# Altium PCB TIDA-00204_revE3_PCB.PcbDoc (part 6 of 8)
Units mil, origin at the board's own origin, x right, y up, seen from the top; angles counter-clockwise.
Board outline 4600 x 3740 mil, 8 copper layers (TopLayer - S1 (.GTL), MidLayer1 - S2 (.G1), MidLayer2 - S3 (.G2), MidLayer3 - S4 (.G3), MidLayer4 - S5 (.G4), MidLayer5 - S6 (.G5), MidLayer6 - S7 (.G6), BottomLayer - S8 (.GBL)), stack 58.938 mil thick; 536 components, 354 nets, 2015 pads, 1067 vias.
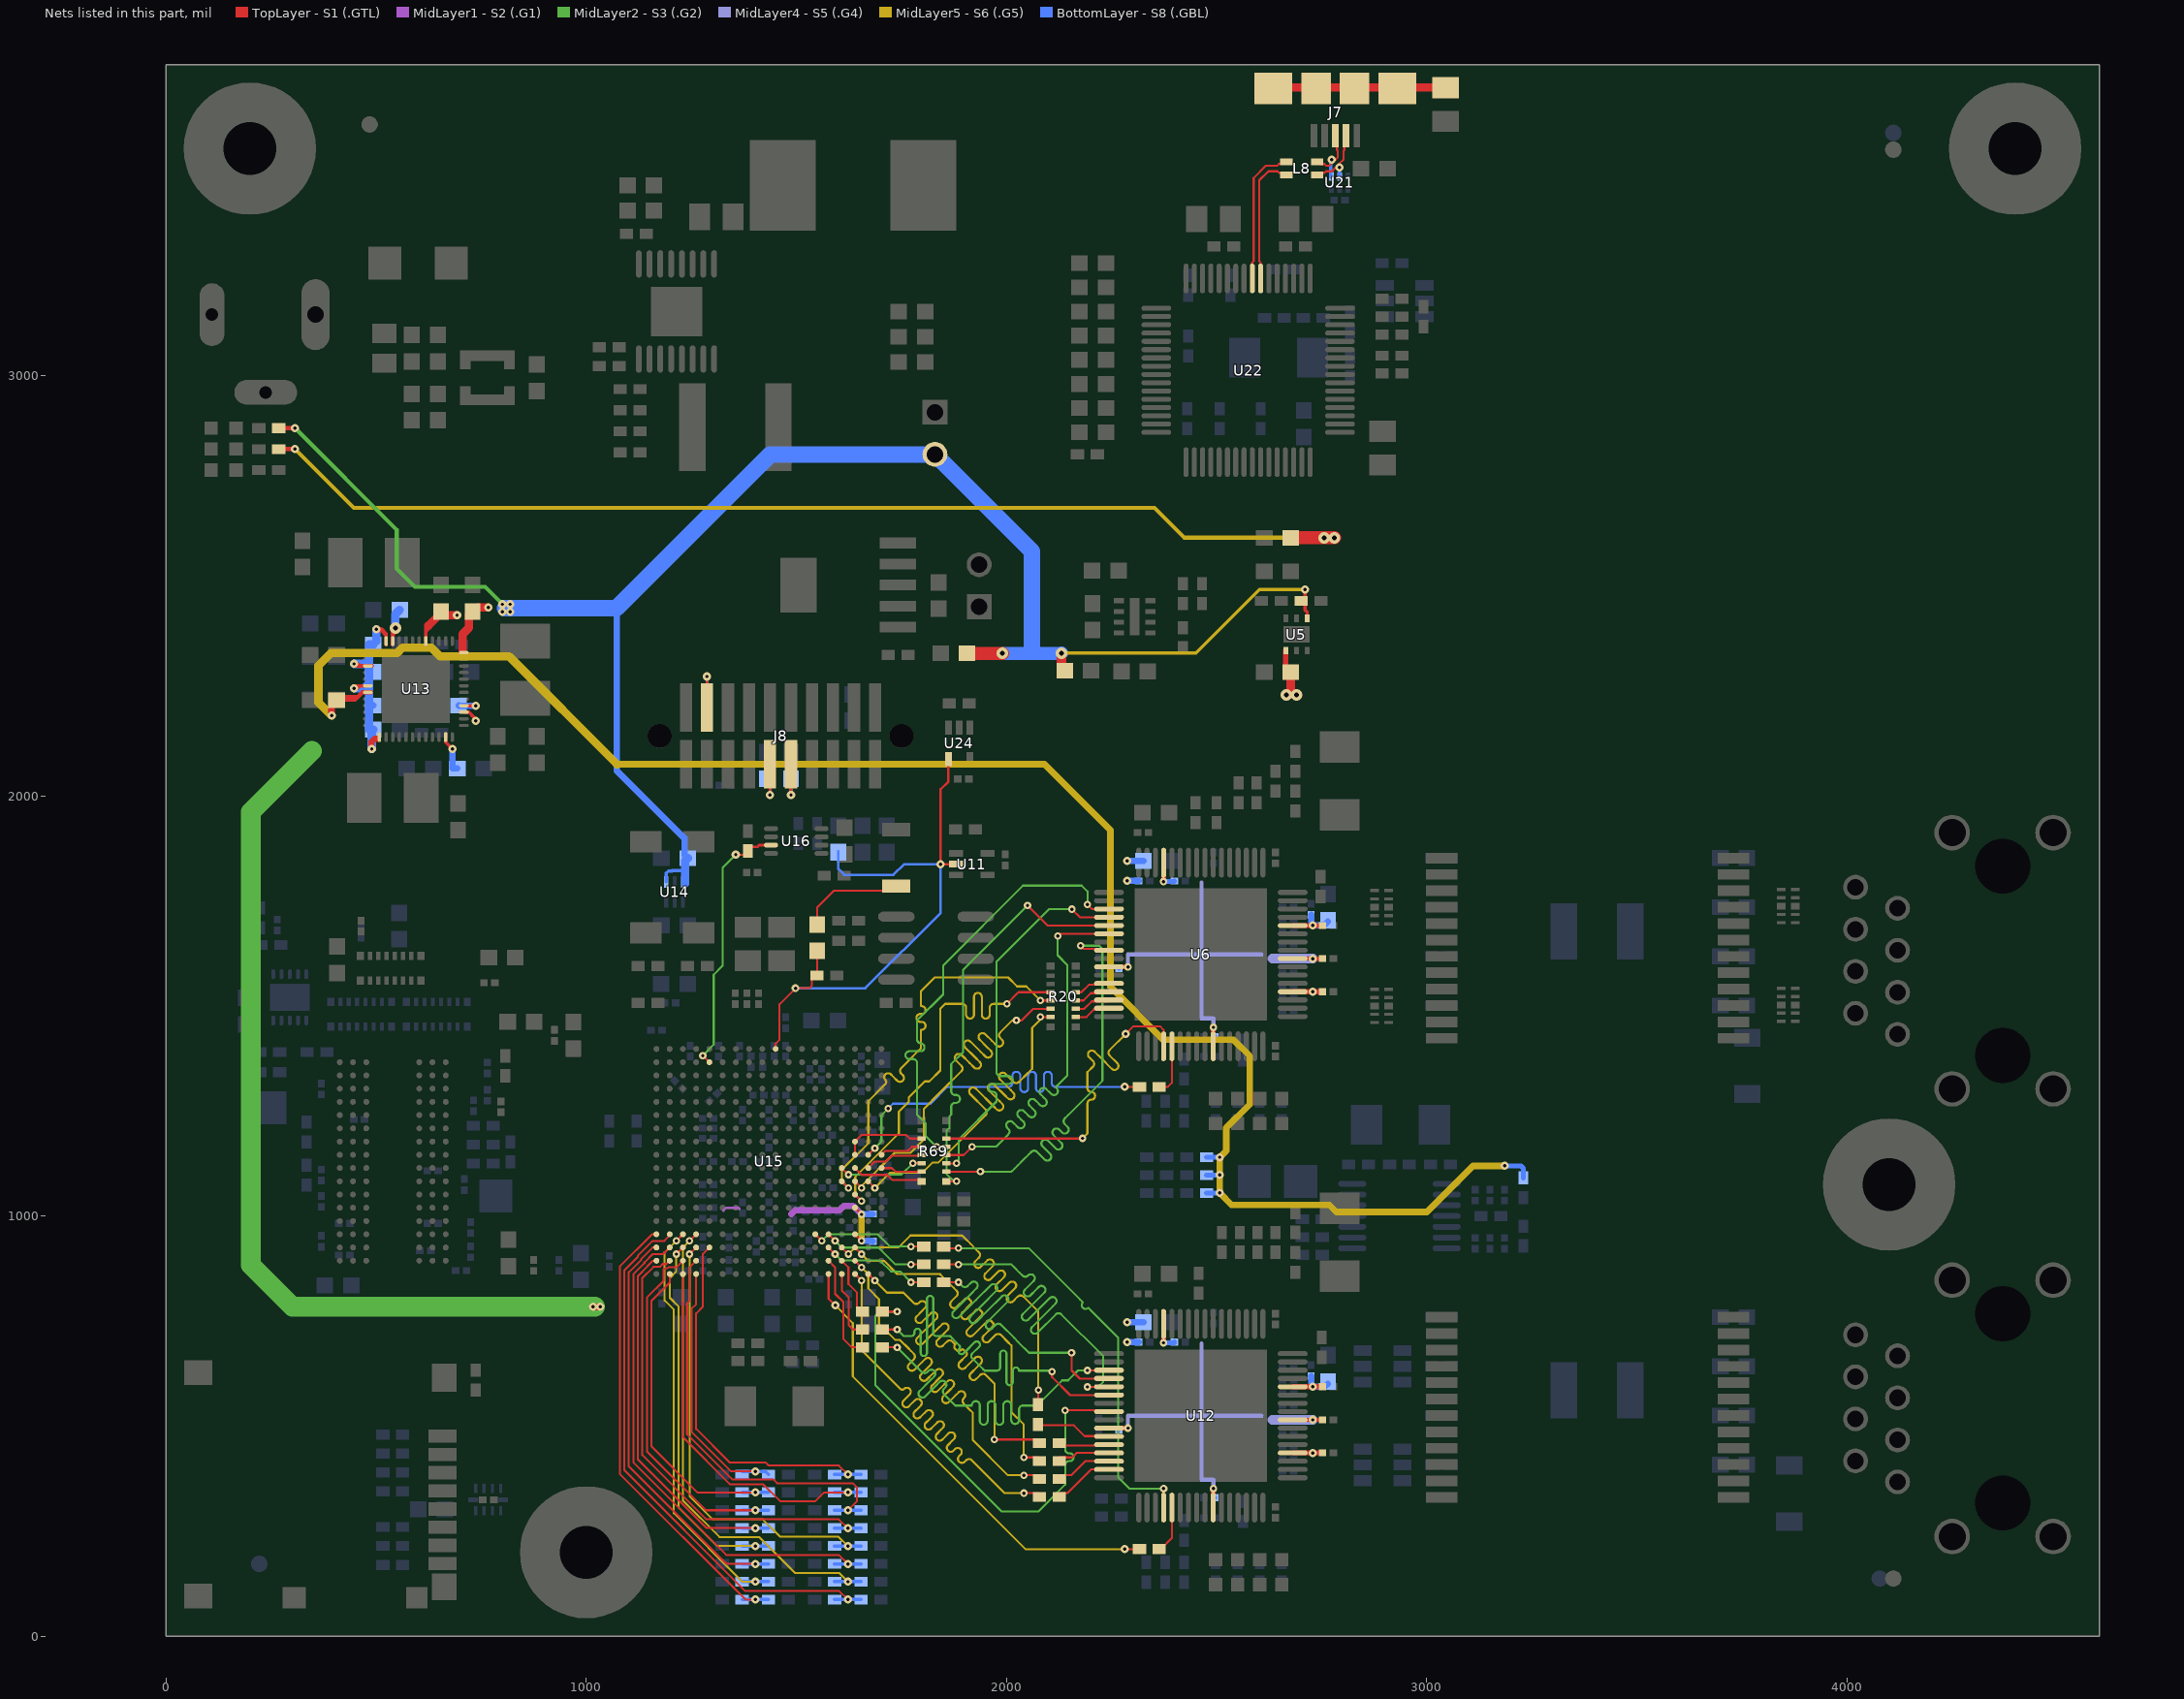
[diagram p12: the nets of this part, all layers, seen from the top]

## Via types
v1: diameter 19.68, hole 7.87, TopLayer - S1 (.GTL) to BottomLayer - S8 (.GBL), 600 vias
v2: diameter 17.72, hole 7.87, TopLayer - S1 (.GTL) to BottomLayer - S8 (.GBL), 408 vias
v3: diameter 27.56, hole 11.81, TopLayer - S1 (.GTL) to BottomLayer - S8 (.GBL), 31 vias
v4: diameter 20, hole 7.87, TopLayer - S1 (.GTL) to BottomLayer - S8 (.GBL), tented both sides, 11 vias
v5: diameter 15.75, hole 7.87, TopLayer - S1 (.GTL) to BottomLayer - S8 (.GBL), 9 vias
v6: diameter 20, hole 7.87, TopLayer - S1 (.GTL) to BottomLayer - S8 (.GBL), 5 vias
v7: diameter 15, hole 7.87, TopLayer - S1 (.GTL) to BottomLayer - S8 (.GBL), 2 vias
v8: diameter 18, hole 7.87, TopLayer - S1 (.GTL) to BottomLayer - S8 (.GBL), 1 vias

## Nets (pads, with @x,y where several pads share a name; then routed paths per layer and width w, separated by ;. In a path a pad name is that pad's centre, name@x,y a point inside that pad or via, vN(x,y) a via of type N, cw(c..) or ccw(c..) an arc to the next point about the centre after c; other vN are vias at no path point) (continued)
RGMII1_RXCTRL: R19.1 U15.J17 | length 965.7
  TopLayer - S1 (.GTL) w4.92: U15.J17@1671.27,1145.75 1674.87,1149.34 v2(1686.99,1161.5) ; v1(2281.32,1307.5) R19.1@2316.38,1307.5
  MidLayer2 - S3 (.G2) w4.68: v2(1686.99,1161.5) 1702.5,1177 1702.5,1239.9 v2(1718.5,1255.91)
  BottomLayer - S8 (.GBL) w4.92: v2(1718.5,1255.91) 1730.1,1267.5 1819.5,1267.5 1859.5,1307.5 2004.92,1307.5 ccw(c2004.92,1316.85) 2014.27,1316.85 2014.27,1334.04 cw(c2023.62,1334.04) 2023.62,1343.39 cw(c2023.62,1334.04) 2032.97,1334.04 2032.97,1307.5 2032.97,1304.46 ccw(c2042.32,1304.46) 2042.32,1295.11 ccw(c2042.32,1304.46) 2051.67,1304.46 2051.67,1307.5 2051.67,1334.04 cw(c2061.02,1334.04) 2061.02,1343.39 cw(c2061.02,1334.04) 2070.37,1334.04 2070.37,1307.5 2070.37,1304.46 ccw(c2079.72,1304.46) 2079.72,1295.11 ccw(c2079.72,1304.46) 2089.07,1304.46 2089.07,1307.5 2089.07,1334.04 cw(c2098.43,1334.04) 2098.43,1343.39 cw(c2098.43,1334.04) 2107.78,1334.04 2107.78,1316.85 ccw(c2117.13,1316.85) 2117.13,1307.5 2166.34,1307.5 v1(2281.32,1307.5)
RGMII1_RXCTRL_R: R19.2 U6.53 | length 121
  TopLayer - S1 (.GTL) w4.92: R19.2@2363.62,1307.5 2384.27,1307.5 2393.6,1316.83 U6.53@2393.6,1404
RGMII1_RXD0: R20.4 U15.M16 | length 1016.2
  TopLayer - S1 (.GTL) w4.92: U15.M16@1639.72,1051.26 v2(1655.47,1035.51) ; v2(2000.98,1504.92) 2026.08,1530.02 2028.72,1532.66 R20.4@2105.47,1532.66
  MidLayer5 - S6 (.G5) w4.92: v2(1655.47,1035.51) 1640.22,1050.77 1640.22,1093.14 1744.09,1197.02 1744.09,1248.58 1767.76,1272.24 1767.76,1282.52 1805.61,1320.37 1816.44,1320.37 1842.52,1346.46 1842.52,1493.11 1854.33,1504.92 1864.17,1504.92 1894.68,1504.92 cw(c1894.68,1495.57) 1904.04,1495.57 1904.04,1479.22 ccw(c1913.39,1479.22) 1913.39,1469.87 ccw(c1913.39,1479.22) 1922.74,1479.22 1922.74,1504.92 1922.74,1521.79 cw(c1932.09,1521.79) 1932.09,1531.14 cw(c1932.09,1521.79) 1941.44,1521.79 1941.44,1504.92 1941.44,1479.22 ccw(c1950.79,1479.22) 1950.79,1469.87 ccw(c1950.79,1479.22) 1960.14,1479.22 1960.14,1495.57 cw(c1969.49,1495.57) 1969.49,1504.92 v2(2000.98,1504.92)
RGMII1_RXD0_R: R20.13 U6.44 | length 88.1
  TopLayer - S1 (.GTL) w4.92: R20.13@2164.53,1532.66 2178.33,1532.66 2195.87,1550.2 2240.59,1550.2 U6.44@2244,1553.6
RGMII1_RXD1: R20.5 U15.L15 | length 1016.9
  TopLayer - S1 (.GTL) w4.92: U15.L15@1608.23,1082.76 v2(1623.98,1067.01) ; v2(2080.89,1512.97) R20.5@2105.47,1512.97
  MidLayer5 - S6 (.G5) w4.92: v2(1623.98,1067.01) 1608.72,1082.26 1608.72,1110.69 1671.26,1173.23 1671.26,1273.62 1710.14,1312.5 1711.93,1314.29 ccw(c1707.11,1319.11) 1711.93,1323.93 cw(c1718.54,1330.54) 1711.93,1337.16 cw(c1718.54,1330.54) 1725.15,1337.16 1729.97,1332.34 1740.12,1322.19 ccw(c1746.73,1328.8) 1753.34,1322.19 ccw(c1746.73,1328.8) 1753.34,1335.41 1749.81,1338.95 cw(c1756.42,1345.56) 1749.81,1352.17 1760.33,1362.7 1796.26,1398.62 1796.26,1415.35 1796.26,1424.7 1796.26,1441.42 cw(c1798.25,1441.42) 1798.25,1443.41 ccw(c1798.25,1452.76) 1807.6,1452.76 ccw(c1798.25,1452.76) 1798.25,1462.11 1796.26,1462.11 1795.12,1462.11 cw(c1795.12,1471.46) 1785.77,1471.46 cw(c1795.12,1471.46) 1795.12,1480.81 1796.26,1480.81 1798.25,1480.81 ccw(c1798.25,1490.16) 1807.6,1490.16 ccw(c1798.25,1490.16) 1798.25,1499.51 cw(c1798.25,1501.5) 1796.26,1501.5 1796.26,1518.21 1796.26,1534.45 1829.72,1567.91 1882.87,1567.91 1970.47,1567.91 2004.02,1567.91 2025.48,1546.46 2047.4,1546.46 v2(2080.89,1512.97)
RGMII1_RXD1_R: R20.12 U6.45 | length 88.1
  TopLayer - S1 (.GTL) w4.92: R20.12@2164.53,1512.97 2183.25,1512.97 2200.79,1530.51 2240.59,1530.51 U6.45@2244,1533.92
RGMII1_RXD2: R20.6 U15.L16 | length 1009.7
  TopLayer - S1 (.GTL) w4.92: U15.L16@1639.72,1082.76 v2(1655.47,1067.01) ; v2(2023.62,1465.55) 2036.42,1465.55 2064.15,1493.29 R20.6@2105.47,1493.29
  MidLayer5 - S6 (.G5) w4.92: v2(1655.47,1067.01) 1655.47,1071.81 1734.25,1150.59 1771.65,1150.59 1803.35,1182.28 1803.35,1255.03 1841.58,1293.26 1892.67,1344.36 ccw(c1886.06,1350.97) 1892.67,1357.58 1880.18,1370.08 cw(c1886.79,1376.69) 1880.18,1383.3 cw(c1886.79,1376.69) 1893.4,1383.3 1912.51,1364.19 1923.31,1353.39 ccw(c1929.92,1360.01) 1936.53,1353.39 ccw(c1929.92,1360.01) 1936.53,1366.62 1925.73,1377.42 1901.21,1401.94 cw(c1907.82,1408.55) 1901.21,1415.16 cw(c1907.82,1408.55) 1914.43,1415.16 1938.95,1390.64 1949.75,1379.84 ccw(c1956.36,1386.45) 1962.98,1379.84 ccw(c1956.36,1386.45) 1962.98,1393.07 1952.18,1403.86 1936.51,1419.54 cw(c1943.12,1426.15) 1936.51,1432.76 cw(c1943.12,1426.15) 1949.73,1432.76 1965.4,1417.09 1976.2,1406.29 ccw(c1982.81,1412.9) 1989.42,1406.29 ccw(c1982.81,1412.9) 1989.42,1419.51 1985.24,1423.7 cw(c1991.85,1430.31) 1985.24,1436.92 2013.87,1465.55 v2(2023.62,1465.55)
RGMII1_RXD2_R: R20.11 U6.46 | length 88.1
  TopLayer - S1 (.GTL) w4.92: R20.11@2164.53,1493.29 2185.22,1493.29 2202.76,1510.83 2240.59,1510.83 U6.46@2244,1514.23
RGMII1_RXD3: R20.7 U15.L17 | length 1016.2
  TopLayer - S1 (.GTL) w4.92: U15.L17@1671.22,1082.76 v2(1686.97,1067.01) ; v2(2080.89,1473.6) R20.7@2105.47,1473.6
  MidLayer5 - S6 (.G5) w4.92: v2(1686.97,1067.01) 1723.31,1103.35 1800.2,1103.35 1823.82,1126.97 1837.6,1126.97 1917.82,1207.18 1950.74,1240.11 ccw(c1944.13,1246.72) 1950.74,1253.34 1914.12,1289.96 cw(c1920.73,1296.57) 1914.12,1303.19 cw(c1920.73,1296.57) 1927.34,1303.19 1970.58,1259.95 1976.65,1253.87 ccw(c1983.26,1260.48) 1989.88,1253.87 ccw(c1983.26,1260.48) 1989.88,1267.1 1983.8,1273.17 1958.26,1298.71 cw(c1964.87,1305.32) 1958.26,1311.93 cw(c1964.87,1305.32) 1971.49,1311.93 1997.02,1286.39 2003.1,1280.32 ccw(c2009.71,1286.93) 2016.32,1280.32 ccw(c2009.71,1286.93) 2016.32,1293.54 2010.25,1299.62 1984.71,1325.16 cw(c1991.32,1331.77) 1984.71,1338.38 cw(c1991.32,1331.77) 1997.93,1338.38 2016.86,1319.45 ccw(c2023.47,1326.07) 2030.08,1319.45 2036.7,1326.07 2043.31,1332.68 2061.02,1350.39 2061.02,1447.83 2080.89,1467.7 v2(2080.89,1473.6)
RGMII1_RXD3_R: R20.10 U6.47 | length 88.1
  TopLayer - S1 (.GTL) w4.92: R20.10@2164.53,1473.6 2190.14,1473.6 2207.68,1491.14 2240.59,1491.14 U6.47@2244,1494.55
RGMII1_TXCLK: R69.10 U6.40 | length 1066
  TopLayer - S1 (.GTL) w4.92: R69.10@1857.03,1105.79 v2(1938.21,1105.79) ; v2(2176.5,1643.5) 2184.11,1635.89 U6.40@2224.34,1635.89
  MidLayer2 - S3 (.G2) w4.92: v2(1938.21,1105.79) 2012.28,1105.79 2019.68,1113.19 2026.3,1119.8 2039.52,1133.02 2052.74,1146.25 2059.36,1152.86 cw(c2065.97,1146.25) 2072.58,1152.86 2090.71,1134.73 ccw(c2097.32,1141.34) 2103.94,1134.73 ccw(c2097.32,1141.34) 2103.94,1147.95 2085.8,1166.08 cw(c2092.41,1172.69) 2085.8,1179.31 cw(c2092.41,1172.69) 2099.03,1179.31 2117.16,1161.17 ccw(c2123.77,1167.78) 2130.38,1161.17 ccw(c2123.77,1167.78) 2130.38,1174.4 2112.25,1192.53 cw(c2118.86,1199.14) 2112.25,1205.75 cw(c2118.86,1199.14) 2125.47,1205.75 2132.05,1199.18 ccw(c2138.66,1205.79) 2145.27,1199.18 ccw(c2138.66,1205.79) 2145.27,1212.4 2138.7,1218.98 cw(c2145.31,1225.59) 2138.7,1232.2 2146.16,1239.67 2228.35,1321.85 2228.35,1635.83 2220.67,1643.5 v2(2176.5,1643.5)
RGMII1_TXCLK_R: R69.7 U15.K18 | length 98.8
  TopLayer - S1 (.GTL) w4.92: U15.K18@1702.72,1114.25 1727.28,1114.25 1735.75,1105.79 R69.7@1797.97,1105.79
RGMII1_TXCTRL: R69.14 U6.52 | length 904.4
  TopLayer - S1 (.GTL) w4.92: R69.14@1857.03,1184.53 2180.59,1184.53 v2(2181.1,1185.04) ; v1(2283.46,1433.07) 2302.17,1451.77 2365.16,1451.77 2373.92,1443.01 U6.52@2373.92,1404
  MidLayer5 - S6 (.G5) w4.92: v2(2181.1,1185.04) 2192.72,1196.65 2192.72,1253.94 2192.72,1267.97 cw(c2201.62,1267.97) 2201.62,1276.87 ccw(c2201.62,1286.22) 2210.97,1286.22 ccw(c2201.62,1286.22) 2201.62,1295.57 cw(c2201.62,1304.47) 2192.72,1304.47 2192.72,1314.27 2192.72,1332.97 2192.72,1342.32 2205.9,1355.51 ccw(c2199.29,1362.12) 2205.9,1368.73 2196.69,1377.94 cw(c2203.3,1384.55) 2196.69,1391.16 cw(c2203.3,1384.55) 2209.92,1391.16 2225.74,1375.34 2250.48,1350.6 ccw(c2257.09,1357.21) 2263.7,1350.6 ccw(c2257.09,1357.21) 2263.7,1363.82 2245.57,1381.95 cw(c2252.18,1388.57) 2245.57,1395.18 v1(2283.46,1433.07)
RGMII1_TXCTRL_R: R69.3 U15.H16 U15.J16 | length 199.8
  TopLayer - S1 (.GTL) w4.92: U15.J16@1639.72,1145.75 U15.H16@1639.72,1177.24 1655.48,1193 1761.72,1193 1770.2,1184.53 R69.3@1797.97,1184.53
RGMII1_TXD0: R69.12 U6.38 | length 1050
  TopLayer - S1 (.GTL) w4.68: v2(2122.05,1666.34) 2127.42,1671.71 2209.71,1671.71 U6.38@2216.54,1671.71
  TopLayer - S1 (.GTL) w4.92: R69.12@1857.03,1145.16 1898.35,1145.16 v2(1918.21,1165.02) ; U6.38@2209.71,1671.71 U6.38@2244,1671.71
  MidLayer2 - S3 (.G2) w4.92: v2(1918.21,1165.02) 1975.06,1165.02 2004.43,1194.39 ccw(c1997.82,1201) 2004.43,1207.61 2002.17,1209.87 cw(c2008.78,1216.49) 2002.17,1223.1 cw(c2008.78,1216.49) 2015.39,1223.1 2024.26,1214.22 2027.05,1211.44 ccw(c2033.66,1218.05) 2040.27,1211.44 ccw(c2033.66,1218.05) 2040.27,1224.67 2037.49,1227.45 2028.62,1236.32 cw(c2035.23,1242.93) 2028.62,1249.54 cw(c2035.23,1242.93) 2041.84,1249.54 2050.71,1240.67 2053.49,1237.89 ccw(c2060.11,1244.5) 2066.72,1237.89 ccw(c2060.11,1244.5) 2066.72,1251.11 2063.93,1253.9 2055.06,1262.77 cw(c2061.67,1269.38) 2055.06,1275.99 cw(c2061.67,1269.38) 2068.29,1275.99 2077.16,1267.12 2079.94,1264.34 ccw(c2086.55,1270.95) 2093.16,1264.34 ccw(c2086.55,1270.95) 2093.16,1277.56 2090.38,1280.34 2081.51,1289.21 cw(c2088.12,1295.83) 2081.51,1302.44 cw(c2088.12,1295.83) 2094.73,1302.44 2103.6,1293.57 2106.39,1290.78 ccw(c2113,1297.39) 2119.61,1290.78 ccw(c2113,1297.39) 2119.61,1304.01 cw(c2122.39,1306.79) 2119.61,1309.57 2131.89,1321.85 2144.79,1334.75 2144.79,1597.54 2121.58,1620.75 v2@2121.58,1666.25
RGMII1_TXD0_R: R69.5 U15.K17 | length 137.5
  TopLayer - S1 (.GTL) w4.92: U15.K17@1671.22,1114.25 1686.97,1130 1713.45,1130 1727.15,1143.7 R69.5@1796.52,1143.7
RGMII1_TXD1: R69.9 U6.37 | length 1011.3
  TopLayer - S1 (.GTL) w4.92: R69.9@1857.03,1082.66 v2(1881.61,1082.66) ; v2@2052.17,1737.2 2097.97,1691.4 U6.37@2244,1691.4
  MidLayer2 - S3 (.G2) w4.92: v2(1881.61,1082.66) 1875.04,1082.66 1857.3,1100.41 1857.3,1202.88 1864.78,1210.36 1864.78,1237.63 1868.58,1241.44 1868.58,1250.79 1868.58,1260.14 cw(c1877.93,1260.14) 1877.93,1269.49 1880.05,1269.49 ccw(c1880.05,1278.84) 1889.4,1278.84 ccw(c1880.05,1278.84) 1880.05,1288.19 1877.93,1288.19 cw(c1877.93,1297.54) 1868.58,1297.54 1868.58,1345.47 1868.58,1361.69 1896.65,1389.76 1896.65,1585.63 v2(2050.2,1739.17)
RGMII1_TXD1_R: R69.8 U15.K16 | length 167.2
  TopLayer - S1 (.GTL) w4.92: U15.K16@1639.72,1114.25 1655.98,1098 1716.96,1098 1729.33,1085.63 R69.8@1795,1085.63
RGMII1_TXD2: R69.11 U6.36 | length 959.5
  TopLayer - S1 (.GTL) w4.68: v2(2155.51,1730.32) 2174.74,1711.08
  TopLayer - S1 (.GTL) w4.92: R69.11@1857.03,1125.47 v2(1881.61,1125.47) ; 2174.74,1711.08 U6.36@2244,1711.08
  MidLayer2 - S3 (.G2) w4.92: v2(1881.61,1125.47) 1886.81,1130.67 1886.81,1183.01 1976.38,1272.57 1976.38,1286.42 ccw(c1967.03,1286.42) 1967.03,1295.77 cw(c1967.03,1305.12) 1957.68,1305.12 cw(c1967.03,1305.12) 1967.03,1314.47 1976.38,1314.47 2004.58,1314.47 ccw(c2004.58,1323.82) 2013.93,1323.82 ccw(c2004.58,1323.82) 2004.58,1333.17 1985.73,1333.17 cw(c1985.73,1342.52) 1976.38,1342.52 1976.38,1396.65 1976.38,1605.32 2101.38,1730.32 v2(2155.51,1730.32)
RGMII1_TXD2_R: R69.6 U15.K15 | length 207.2
  TopLayer - S1 (.GTL) w4.92: U15.K15@1608.23,1114.25 v2(1623.98,1098.5) ; v2(1777.56,1125.98) R69.6@1797.46,1125.98
  MidLayer2 - S3 (.G2) w4.68: v2(1623.98,1098.5) 1750.08,1098.5 v2(1777.56,1125.98)
RGMII1_TXD3: R69.13 U6.35 | length 1083.7
  TopLayer - S1 (.GTL) w4.92: v2(1833.66,1164.37) 1834.13,1164.84 R69.13@1857.03,1164.84 ; v2(2192.91,1741.14) 2203.29,1730.77 U6.35@2244,1730.77
  MidLayer2 - S3 (.G2) w4.92: v2(1833.66,1164.37) 1808.27,1189.76 1808.27,1220.47 1787.4,1241.35 1787.4,1364.17 ccw(c1778.05,1364.17) 1778.05,1373.52 1769.16,1373.52 cw(c1769.16,1382.87) 1759.81,1382.87 cw(c1769.16,1382.87) 1769.16,1392.22 1787.4,1392.22 1795.59,1392.22 ccw(c1795.59,1401.57) 1804.94,1401.57 ccw(c1795.59,1401.57) 1795.59,1410.93 1796.74,1410.93 cw(c1796.75,1420.28) 1787.4,1420.28 1787.4,1429.13 1787.4,1465.55 1849.41,1527.56 1849.41,1596.46 2039.37,1786.42 2179.13,1786.42 2192.91,1772.64 v2(2192.91,1741.14)
RGMII1_TXD3_R: R69.4 U15.J18 | length 103.2
  TopLayer - S1 (.GTL) w4.92: U15.J18@1702.72,1145.75 1711.97,1155 1765.24,1155 1775.08,1164.84 R69.4@1797.97,1164.84
RGMII2_RXCLK: R44.1 U15.T15 | length 1047.9
  TopLayer - S1 (.GTL) w4.92: U15.T15@1608.23,925.28 v2@1623.95,909.57 ; v2@2075.79,585.04 2075.79,548.23 R44.1@2076.38,547.64
  MidLayer5 - S6 (.G5) w4.92: v2(1623.97,909.55) 1639.62,925.2 1743.11,925.2 1771.65,953.74 1894.68,953.74 1901.3,947.13 1914.52,933.91 1927.74,920.68 1934.36,914.07 cw(c1927.74,907.46) 1934.36,900.85 1926.03,892.53 ccw(c1932.65,885.91) 1926.03,879.3 ccw(c1932.65,885.91) 1939.26,879.3 1954.19,894.23 cw(c1960.8,887.62) 1967.41,894.23 cw(c1960.8,887.62) 1967.41,881.01 1950.1,863.69 ccw(c1956.71,857.08) 1950.1,850.47 ccw(c1956.71,857.08) 1963.32,850.47 1980.64,867.79 cw(c1987.25,861.18) 1993.86,867.79 cw(c1987.25,861.18) 1993.86,854.56 1976.54,837.25 ccw(c1983.15,830.63) 1976.54,824.02 ccw(c1983.15,830.63) 1989.77,824.02 2007.08,841.34 cw(c2013.7,834.73) 2020.31,841.34 cw(c2013.7,834.73) 2020.31,828.12 2002.99,810.8 ccw(c2009.6,804.19) 2002.99,797.58 ccw(c2009.6,804.19) 2016.21,797.58 2026.92,808.28 cw(c2033.53,801.67) 2040.14,808.28 2072.34,776.08 2075.79,772.64 v2(2075.79,585.63)
RGMII2_RXCLK_R: R44.2 U12.43 | length 155.3
  TopLayer - S1 (.GTL) w4.92: R44.2@2082.61,501.43 2083.14,501.97 2160.43,501.97 2186.02,476.38 2226.25,476.38 U12.43@2226.84,475.79
RGMII2_RXCTRL: R43.1 U15.V14 | length 1119.9
  TopLayer - S1 (.GTL) w4.92: U15.V14@1576.73,862.28 1576.73,803.27 v1(1592.5,787.5) ; v1(2281.32,207.5) R43.1@2316.38,207.5
  MidLayer5 - S6 (.G5) w4.68: v1(1592.5,787.5) 1634.5,745.5 1634.5,618.45 2045.45,207.5 v1(2281.32,207.5)
RGMII2_RXCTRL_R: R43.2 U12.53 | length 113.7
  TopLayer - S1 (.GTL) w4.92: R43.2@2363.62,207.5 2367.5,207.5 2393.6,233.6 U12.53@2393.6,306.5
RGMII2_RXD0: R46.1 U15.V17 | length 1108.8
  TopLayer - S1 (.GTL) w4.92: U15.V17@1671.22,862.28 v2(1686.97,846.56) ; v2(1971.46,468.5) 1971.63,468.33 R46.1@2076.38,468.33
  MidLayer5 - S6 (.G5) w4.92: v2(1686.97,846.56) 1715.61,817.91 1754.92,817.91 1779.04,793.8 ccw(c1785.65,800.41) 1792.26,793.8 1793.4,794.94 cw(c1800.02,788.33) 1806.63,794.94 cw(c1800.02,788.33) 1806.63,781.72 1798.87,773.96 1786.39,761.48 ccw(c1793,754.87) 1786.39,748.26 ccw(c1793,754.87) 1799.61,748.26 1812.09,760.74 1819.85,768.5 cw(c1826.46,761.89) 1833.08,768.5 cw(c1826.46,761.89) 1833.08,755.28 1825.32,747.52 1788.01,710.21 ccw(c1794.62,703.6) 1788.01,696.99 ccw(c1794.62,703.6) 1801.23,696.99 1838.54,734.29 1846.3,742.05 cw(c1852.91,735.44) 1859.52,742.05 cw(c1852.91,735.44) 1859.52,728.83 1851.76,721.07 1835.81,705.11 ccw(c1842.42,698.5) 1835.81,691.89 ccw(c1842.42,698.5) 1849.03,691.89 1858.38,701.24 cw(c1864.99,694.62) 1871.6,701.23 1878.21,694.62 ccw(c1883.68,689.16) 1878.21,683.7 1880.51,681.4 ccw(c1885.97,686.86) 1891.43,681.4 cw(c1895.03,677.8) 1898.63,681.4 1904.66,675.37 cw(c1901.06,671.77) 1904.66,668.18 1888.7,652.22 ccw(c1895.31,645.61) 1888.7,639 ccw(c1895.31,645.61) 1901.92,639 1917.88,654.95 1925.64,662.71 cw(c1932.25,656.1) 1938.86,662.71 cw(c1932.25,656.1) 1938.86,649.49 1931.11,641.73 1915.15,625.77 ccw(c1921.76,619.16) 1915.15,612.55 ccw(c1921.76,619.16) 1928.37,612.55 1937.72,621.89 cw(c1944.33,615.28) 1950.94,621.89 1969,603.84 1971.46,601.38 v2(1971.46,468.5)
RGMII2_RXD0_R: R46.2 U12.44 | length 127.4
  TopLayer - S1 (.GTL) w4.92: R46.2@2123.62,468.33 2138.21,453.74 2241.63,453.74 U12.44@2244,456.1
RGMII2_RXD1: R47.1 U15.T16 | length 1103.2
  TopLayer - S1 (.GTL) w4.92: U15.T16@1639.72,925.28 v2(1655.47,909.53) ; v2(2041.32,425.83) R47.1@2076.38,425.83
  MidLayer5 - S6 (.G5) w4.92: v2(1655.47,909.53) 1671.69,893.31 1709.05,893.31 1740.16,862.2 1841.54,862.2 1848.15,855.59 1861.37,842.37 1874.59,829.15 1881.21,822.53 cw(c1874.59,815.92) 1881.21,809.31 1868.75,796.86 ccw(c1875.37,790.25) 1868.75,783.64 ccw(c1875.37,790.25) 1881.98,783.64 1901.04,802.7 cw(c1906.14,797.6) 1911.24,802.7 1914.26,799.68 cw(c1909.16,794.58) 1914.26,789.48 1895.2,770.41 ccw(c1901.81,763.8) 1895.2,757.19 ccw(c1901.81,763.8) 1908.42,757.19 1927.49,776.25 cw(c1932.59,771.15) 1937.69,776.25 1940.71,773.23 cw(c1935.61,768.13) 1940.71,763.03 1907.58,729.9 ccw(c1914.19,723.29) 1907.58,716.68 ccw(c1914.19,723.29) 1920.81,716.68 1953.93,749.81 cw(c1959.03,744.71) 1964.13,749.81 1967.16,746.78 cw(c1962.06,741.68) 1967.16,736.58 1945.89,715.31 ccw(c1952.5,708.7) 1945.89,702.09 ccw(c1952.5,708.7) 1959.11,702.09 1973.77,716.75 cw(c1980.38,710.13) 1986.99,716.75 2002.95,700.79 2011.81,691.93 2011.81,533.46 2041.32,503.96 v2(2041.32,425.83)
RGMII2_RXD1_R: R47.2 U12.45 | length 124.8
  TopLayer - S1 (.GTL) w4.92: R47.2@2123.62,425.83 2156.14,425.83 2166.73,436.42 U12.45@2244,436.42
RGMII2_RXD2: R50.1 U15.U16 | length 1108.9
  TopLayer - S1 (.GTL) w4.92: U15.U16@1639.72,893.78 v2@1655.45,878.07 ; v2(2041.32,383.33) R50.1@2076.38,383.33
  MidLayer5 - S6 (.G5) w4.92: v2(1655.47,878.05) 1671.26,862.26 1671.26,827.76 1696.85,802.17 1696.85,744.09 1735.99,704.96 1747.04,704.96 1766.35,685.64 ; 1749.02,702.98 1766.35,685.64 ; v2(2041.32,383.33) 2003.48,383.33 1920.28,466.54 1920.28,531.72 1911.53,540.47 1898.59,553.41 cw(c1905.2,560.02) 1898.59,566.63 1899.26,567.3 ccw(c1892.65,573.92) 1899.26,580.53 ccw(c1892.65,573.92) 1886.04,580.53 1878.75,573.24 1862.91,557.41 cw(c1856.3,564.02) 1849.69,557.41 cw(c1856.3,564.02) 1849.69,570.63 1865.53,586.47 1872.81,593.75 ccw(c1866.2,600.36) 1872.81,606.98 ccw(c1866.2,600.36) 1859.59,606.98 1852.3,599.69 1836.47,583.85 cw(c1829.86,590.47) 1823.24,583.85 cw(c1829.86,590.47) 1823.24,597.08 1839.08,612.91 1846.37,620.2 ccw(c1839.75,626.81) 1846.37,633.42 ccw(c1839.75,626.81) 1833.14,633.42 1825.86,626.14 1810.38,610.66 cw(c1803.77,617.28) 1797.16,610.66 cw(c1803.77,617.28) 1797.16,623.89 1812.63,639.36 1819.92,646.65 ccw(c1813.31,653.26) 1819.92,659.87 ccw(c1813.31,653.26) 1806.69,659.87 1799.41,652.58 1781.45,634.62 cw(c1774.84,641.23) 1768.23,634.62 cw(c1774.84,641.23) 1768.23,647.85 1779.57,659.2 ccw(c1772.96,665.81) 1779.57,672.42 1772.96,679.03 1766.35,685.64
RGMII2_RXD2_R: R50.2 U12.46 | length 134.2
  TopLayer - S1 (.GTL) w4.92: R50.2@2123.62,383.33 2154,383.33 2187.4,416.73 U12.46@2244,416.73
RGMII2_RXD3: R51.1 U15.V16 | length 1084.3
  TopLayer - S1 (.GTL) w4.92: U15.V16@1639.76,862.28 v2(1655.46,846.58) ; v2(2041.32,340.83) R51.1@2076.38,340.83
  MidLayer5 - S6 (.G5) w4.92: v2(1655.46,846.58) 1655.46,681.15 1745.57,591.04 1747.78,588.83 ccw(c1752.18,593.24) 1756.58,588.83 cw(c1763.2,582.22) 1769.81,588.83 cw(c1763.2,582.22) 1769.81,575.61 1765.41,571.21 1755.16,560.96 ccw(c1761.77,554.35) 1755.16,547.74 ccw(c1761.77,554.35) 1768.38,547.74 1778.63,557.98 1782.67,562.02 cw(c1789.28,555.41) 1795.89,562.02 cw(c1789.28,555.41) 1795.89,548.8 1791.85,544.76 1781.61,534.51 ccw(c1788.22,527.9) 1781.61,521.29 ccw(c1788.22,527.9) 1794.83,521.29 1805.08,531.54 1809.12,535.58 cw(c1815.73,528.96) 1822.34,535.58 cw(c1815.73,528.96) 1822.34,522.35 1818.3,518.31 1808.05,508.07 ccw(c1814.66,501.46) 1808.05,494.84 ccw(c1814.66,501.46) 1821.28,494.84 1831.52,505.09 1835.56,509.13 cw(c1842.17,502.52) 1848.79,509.13 cw(c1842.17,502.52) 1848.79,495.91 1844.75,491.87 1834.5,481.62 ccw(c1841.11,475.01) 1834.5,468.4 ccw(c1841.11,475.01) 1847.72,468.4 1857.97,478.64 1862.01,482.68 cw(c1868.62,476.07) 1875.23,482.68 cw(c1868.62,476.07) 1875.23,469.46 1871.19,465.42 1860.95,455.17 ccw(c1867.56,448.56) 1860.95,441.95 ccw(c1867.56,448.56) 1874.17,441.95 1877.81,445.59 cw(c1884.42,438.97) 1891.03,445.59 cw(c1884.42,438.97) 1891.03,432.36 1887.39,428.73 ccw(c1894,422.11) 1887.39,415.5 ccw(c1894,422.11) 1900.62,415.5 1904.25,419.14 cw(c1910.86,412.53) 1917.48,419.14 1928.64,407.97 1995.79,340.83 v2(2041.32,340.83)
RGMII2_RXD3_R: R51.2 U12.47 | length 143.7
  TopLayer - S1 (.GTL) w4.92: R51.2@2123.62,340.83 2144.96,340.83 2201.18,397.05 U12.47@2244,397.05
RGMII2_TXCLK: R82.2 U12.40 | length 1145.8
  TopLayer - S1 (.GTL) w4.92: R82.2@1704.84,772.73 v2(1739.9,772.73) ; v2@2137.8,537.4 2138.78,538.39 U12.40@2224.34,538.39
  MidLayer2 - S3 (.G2) w4.92: v2(1739.9,772.73) 1698.91,772.73 1687.99,761.81 1687.99,597.44 1988.19,297.24 2075.79,297.24 2139.76,361.22 2139.76,407.48 cw(c2149.11,407.48) 2149.11,416.83 2150.52,416.83 ccw(c2150.52,426.18) 2159.87,426.18 ccw(c2150.52,426.18) 2150.52,435.53 2149.11,435.53 cw(c2149.11,444.88) 2139.76,444.88 v2(2139.76,537.4)
RGMII2_TXCLK_R: R82.1 U15.U15 | length 146.3
  TopLayer - S1 (.GTL) w4.92: U15.U15@1608.23,893.78 1623.99,878.04 1623.99,838.61 1644.68,817.91 1644.68,777.56 1649.51,772.73 R82.1@1657.6,772.73
RGMII2_TXCTRL: R77.2 U12.52 | length 1009.9
  TopLayer - S1 (.GTL) w4.92: R77.2@1850.78,923.56 v2(1885.84,923.56) ; U12.52@2373.92,306.5 2373.92,350.92 v2@2374,351
  MidLayer2 - S3 (.G2) w4.68: v2(1885.84,923.56) 2052.81,923.56 2175.2,801.18 2181.7,794.68 ccw(c2188.12,788.25) 2181.69,781.83 ; 2181.7,781.82 2181.89,781.63 ccw(c2188.32,788.06) 2194.75,781.63 2201.28,775.1 2265.75,710.63 2265.75,378.15 2292.4,351.5 v2(2374,351.5)
RGMII2_TXCTRL_R: R77.1 U15.R13 | length 283.5
  TopLayer - S1 (.GTL) w4.92: U15.R13@1545.24,956.77 v2(1560.98,941.02) ; v2(1773.16,927.5) R77.1@1803.54,927.5
  MidLayer2 - S3 (.G2) w4.68: v2(1560.98,941.02) 1576.73,956.77 1693.73,956.77 1723,927.5 v2(1773.16,927.5)
RGMII2_TXD0: R81.2 U12.38 | length 1147.3
  TopLayer - S1 (.GTL) w4.92: R81.2@1704.84,730.23 v2(1739.9,730.23) ; v2(2108.27,629.92) 2108.27,617.13 2151.48,573.92 U12.38@2244,573.92
  MidLayer2 - S3 (.G2) w4.92: v2(1739.9,730.23) 1755.57,714.57 1773.62,714.57 ccw(c1773.62,722.03) 1781.08,722.03 1781.08,724.49 cw(c1788.54,724.49) 1788.54,731.95 cw(c1788.54,724.49) 1796,724.49 1796,714.57 1796,674.4 ccw(c1803.46,674.4) 1803.46,666.94 ccw(c1803.46,674.4) 1810.93,674.4 1810.93,714.57 1810.93,802.64 cw(c1818.39,802.64) 1818.39,810.1 cw(c1818.39,802.64) 1825.85,802.64 1825.85,722.03 ccw(c1833.31,722.03) 1833.31,714.57 1840.77,714.57 1855.69,714.57 1865.52,714.57 1870.79,709.29 1881.34,698.74 1887.88,692.2 cw(c1883.87,688.19) 1887.88,684.18 ccw(c1893.16,678.9) 1887.88,673.63 ccw(c1893.16,678.9) 1898.43,673.63 1902.44,677.64 1924.3,699.49 cw(c1929.57,694.22) 1934.85,699.49 cw(c1929.57,694.22) 1934.85,688.94 1918.27,672.36 ccw(c1923.55,667.09) 1918.27,661.81 1923.55,656.54 1934.1,645.99 1944.65,635.43 1947.83,632.25 1955.3,632.25 1970.22,632.25 1977.68,632.25 ccw(c1977.68,639.71) 1985.14,639.71 1985.14,672.45 cw(c1992.6,672.45) 1992.6,679.91 cw(c1992.6,672.45) 2000.06,672.45 2000.06,632.25 2000.06,604.98 ccw(c2007.52,604.98) 2007.52,597.52 ccw(c2007.52,604.98) 2014.98,604.98 2014.98,632.25 cw(c2022.44,632.25) 2022.44,639.71 cw(c2022.44,632.25) 2029.9,632.25 2029.9,633.48 ccw(c2031.13,633.48) 2031.13,632.25 2081.69,632.25 v2@2105.94,632.25
RGMII2_TXD0_R: R81.1 U15.V15 | length 165.8
  TopLayer - S1 (.GTL) w4.92: U15.V15@1608.23,862.28 1608.23,822.87 1625,806.1 1625,740.07 1634.84,730.23 R81.1@1657.6,730.23
RGMII2_TXD1: R80.2 U12.37 | length 1041.2
  TopLayer - S1 (.GTL) w4.92: R80.2@1850.78,885 v2(1885.84,885) ; v2(2192.5,593.5) U12.37@2245.1,593.5
  MidLayer2 - S3 (.G2) w4.92: v2(1885.84,885) 1960.53,885 1969.88,885 1988.58,885 2007.28,885 2011.65,885 2018.27,878.39 2031.49,865.16 2038.1,858.55 ccw(c2044.71,865.16) 2051.32,858.55 cw(c2057.94,851.94) 2064.55,858.55 cw(c2057.94,851.94) 2064.55,845.33 2057.94,838.72 2043.94,824.72 ccw(c2050.55,818.11) 2043.94,811.5 ccw(c2050.55,818.11) 2057.16,811.5 2071.16,825.49 2076.81,831.14 cw(c2083.42,824.53) 2090.03,831.14 cw(c2083.42,824.53) 2090.03,817.92 2084.38,812.27 2039.32,767.21 ccw(c2045.93,760.6) 2039.32,753.99 ccw(c2045.93,760.6) 2052.55,753.99 2097.61,799.05 2103.25,804.7 cw(c2109.87,798.08) 2116.48,804.7 cw(c2109.87,798.08) 2116.48,791.47 2110.83,785.82 2060.97,735.96 ccw(c2067.58,729.35) 2060.97,722.74 ccw(c2067.58,729.35) 2074.19,722.74 2117.44,765.99 cw(c2124.05,759.38) 2130.66,765.99 2230.32,666.34 2230.32,605.32 2218.5,593.5 v2(2192.5,593.5)
RGMII2_TXD1_R: R80.1 U15.R14 | length 256.6
  TopLayer - S1 (.GTL) w4.92: U15.R14@1576.73,956.77 v2(1592.48,941.02) ; v2(1773.16,885) R80.1@1803.54,885
  MidLayer2 - S3 (.G2) w4.68: v2(1592.48,941.02) 1608.5,925 1695.5,925 1735.5,885 v2(1773.16,885)
RGMII2_TXD2: R79.2 U12.36 | length 1035.5
  TopLayer - S1 (.GTL) w4.92: R79.2@1850.78,842.5 v2(1885.84,842.5) ; v2(2155,674.69) 2155,632.75 2174.58,613.17 U12.36@2244,613.17
  MidLayer2 - S3 (.G2) w4.92: v2(1885.84,842.5) 1894.68,833.66 ccw(c1901.29,840.27) 1907.9,833.66 1915.64,841.39 cw(c1922.25,834.78) 1928.86,841.39 cw(c1922.25,834.78) 1928.86,828.17 1914.52,813.82 1873.78,773.09 ccw(c1880.39,766.48) 1873.78,759.86 ccw(c1880.39,766.48) 1887,759.86 1927.74,800.6 1962.44,835.3 cw(c1969.06,828.69) 1975.67,835.3 cw(c1969.06,828.69) 1975.67,822.08 1940.96,787.38 1914.61,761.02 ccw(c1921.22,754.41) 1914.61,747.8 ccw(c1921.22,754.41) 1927.84,747.8 1954.19,774.15 1988.89,808.86 cw(c1995.5,802.24) 2002.11,808.86 cw(c1995.5,802.24) 2002.11,795.63 1967.41,760.93 1953.24,746.76 ccw(c1959.85,740.15) 1953.24,733.53 ccw(c1959.85,740.15) 1966.46,733.53 1974.02,741.09 cw(c1980.63,734.48) 1987.25,741.09 2018.2,710.13 2028.05,700.29 2053.65,674.69 v2(2155,674.69)
RGMII2_TXD2_R: R79.1 U15.T14 | length 261.1
  TopLayer - S1 (.GTL) w4.92: U15.T14@1576.73,925.28 v2(1592.48,909.53) ; v2(1773.16,842.5) R79.1@1803.54,842.5
  MidLayer2 - S3 (.G2) w4.68: v2(1592.48,909.53) 1608.01,894 1699.5,894 1725.17,868.33 1747.33,868.33 v2(1773.16,842.5)
RGMII2_TXD3: R78.2 U12.35 | length 1059.4
  TopLayer - S1 (.GTL) w4.92: R78.2@1704.84,687.73 v2(1739.9,687.73) ; v2(2192.5,632.75) U12.35@2245.1,632.75
  MidLayer2 - S3 (.G2) w4.92: v2(1739.9,687.73) 1798.7,628.94 ccw(c1805.31,635.55) 1811.92,628.94 1814.79,631.81 cw(c1821.4,625.2) 1828.02,631.81 cw(c1821.4,625.2) 1828.02,618.58 1818.53,609.1 1793.51,584.08 ccw(c1800.12,577.47) 1793.51,570.86 ccw(c1800.12,577.47) 1806.73,570.86 1831.76,595.88 1841.24,605.36 cw(c1847.85,598.75) 1854.46,605.36 cw(c1847.85,598.75) 1854.46,592.14 1851.59,589.27 ccw(c1858.2,582.65) 1851.59,576.04 1877.2,550.43 1878.42,549.21 1900.59,549.21 1916.83,549.21 ccw(c1916.83,550.2) 1917.81,550.2 cw(c1927.17,550.2) 1927.17,559.55 cw(c1927.17,550.2) 1936.52,550.2 1936.52,549.21 1936.52,512.8 ccw(c1945.87,512.8) 1945.87,503.44 ccw(c1945.87,512.8) 1955.22,512.8 1955.22,549.21 1955.22,550.2 cw(c1964.57,550.2) 1964.57,559.55 cw(c1964.57,550.2) 1973.92,550.2 1973.92,549.21 1973.92,512.8 ccw(c1983.27,512.8) 1983.27,503.44 ccw(c1983.27,512.8) 1992.62,512.8 1992.62,549.21 1992.62,550.2 cw(c2001.97,550.2) 2001.97,559.55 cw(c2001.97,550.2) 2011.32,550.2 2011.32,549.21 2011.32,514.76 ccw(c2020.67,514.76) 2020.67,505.41 ccw(c2020.67,514.76) 2030.02,514.76 2030.02,539.86 cw(c2039.37,539.86) 2039.37,549.21 2072.29,549.21 2132.25,609.17 2146.65,609.17 ; 2147.64,610.16 2170.23,632.75 v2(2192.5,632.75)
RGMII2_TXD3_R: R78.1 U15.U14 | length 254.6
  TopLayer - S1 (.GTL) w4.92: U15.U14@1576.73,893.78 1592.52,878.01 1592.52,814.98 1612.2,795.3 1612.2,707.42 1631.89,687.73 R78.1@1657.6,687.73
RTC_PORZ: R119.2 U15.B5 U16.7 | length 626.2
  TopLayer - S1 (.GTL) w4.75: v2(1277.52,1381.97) U15.B5@1293.28,1366.25 ; v1(1356,1860) 1376.12,1860 R119.2@1385,1868.88
  TopLayer - S1 (.GTL) w6: R119.2@1385,1868.88 1395.12,1879 1408,1879 1411.66,1882.66 U16.7@1439.96,1882.66
  MidLayer2 - S3 (.G2) w4.72: v2(1277.52,1381.97) 1303.5,1407.95 1303.5,1574.5 1324.5,1595.5 1324.5,1828.5 v1(1356,1860)
RTCK: J8.9 R159.2 | length 114.6
  TopLayer - S1 (.GTL) w5.91: v1(1437.5,2002.26) J8.9@1437.5,2075
  BottomLayer - S8 (.GBL) w5.91: R159.2@1430,2041 1437.5,2033.5 v1(1437.5,2002.26)
SYS_BOOT0: R98.1 R116.2 U15.R1 | length 1121.6
  TopLayer - S1 (.GTL) w4.72: U15.R1@1167.28,956.77 1156.77,956.77 1080.11,880.11 1080.11,386.43 1379.04,87.5 v1(1402.5,87.5)
  BottomLayer - S8 (.GBL) w8: R98.1@1371.12,87.5 v1(1402.5,87.5) R116.2@1433.88,87.5
SYS_BOOT1: R97.1 R115.2 U15.R2 | length 1344.4
  TopLayer - S1 (.GTL) w4.72: U15.R2@1198.78,956.77 1198.78,953.8 1186,941.02 1158.02,941.02 1122.65,905.65 1122.65,902.46 1090.86,870.67 1090.86,395.36 1377.72,108.5 1601.5,108.5 v1(1622.5,87.5)
  BottomLayer - S8 (.GBL) w8: R115.2@1591.12,87.5 v1(1622.5,87.5) R97.1@1653.88,87.5
SYS_BOOT2: R96.1 R114.2 U15.R3 | length 1014.6
  TopLayer - S1 (.GTL) w4.75: v2(1214.53,941.02) U15.R3@1230.28,956.77
  MidLayer5 - S6 (.G5) w4.75: v2(1214.53,941.02) 1187.01,913.5 1187.01,799.21 1208.82,777.41 1208.82,293.15 1371.97,130 v1(1402.5,130)
  BottomLayer - S8 (.GBL) w8: R96.1@1371.12,130 v1(1402.5,130) R114.2@1433.88,130
SYS_BOOT3: R95.1 R113.2 U15.R4 | length 1181.8
  TopLayer - S1 (.GTL) w4.75: v2(1246.02,941.02) U15.R4@1261.77,956.77
  MidLayer5 - S6 (.G5) w4.75: v2(1246.02,941.02) 1230.32,925.31 1230.32,322.83 1316.93,236.22 1411.42,236.22 1497.05,150.59 1601.91,150.59 v1(1622.5,130)
  BottomLayer - S8 (.GBL) w8: R113.2@1591.12,130 v1(1622.5,130) R95.1@1653.88,130
SYS_BOOT4: R94.1 R112.2 U15.T1 | length 1013.1
  TopLayer - S1 (.GTL) w4.72: U15.T1@1167.28,925.28 1158.28,925.28 1130.65,897.65 1130.65,895.26 1101.61,866.22 1101.61,404.3 1333.41,172.5 v1(1402.5,172.5)
  BottomLayer - S8 (.GBL) w8: R94.1@1371.12,172.5 v1(1402.5,172.5) R112.2@1433.88,172.5
SYS_BOOT5: R93.1 R111.2 U15.T2 | length 1234.2
  TopLayer - S1 (.GTL) w4.72: U15.T2@1198.78,925.28 1183.01,909.53 1158.53,909.53 1138.65,889.65 1138.65,888.06 1112.36,861.76 1112.36,414.22 1333.07,193.5 1601.5,193.5 v1(1622.5,172.5)
  BottomLayer - S8 (.GBL) w8: R111.2@1591.12,172.5 v1(1622.5,172.5) R93.1@1653.88,172.5
SYS_BOOT6: R92.1 R110.2 U15.T3 | length 923.4
  TopLayer - S1 (.GTL) w4.75: v2(1214.53,909.53) U15.T3@1230.28,925.28
  MidLayer5 - S6 (.G5) w4.75: v2(1214.53,909.53) 1214.53,868.14 1199.25,852.86 1199.25,805.67 1219.57,785.36 1219.57,307.01 1311.57,215 v1(1402.5,215)
  BottomLayer - S8 (.GBL) w8: R92.1@1371.12,215 v1(1402.5,215) R110.2@1433.88,215
SYS_BOOT7: R91.1 R109.2 U15.T4 | length 1086.5
  TopLayer - S1 (.GTL) w4.75: v2(1246.02,909.53) U15.T4@1261.77,925.28
  MidLayer5 - S6 (.G5) w4.75: v2(1246.02,909.53) 1246.02,333.7 1301.18,278.54 1420.28,278.54 1461.61,237.2 1600.3,237.2 v1(1622.5,215)
  BottomLayer - S8 (.GBL) w8: R109.2@1591.12,215 v1(1622.5,215) R91.1@1653.88,215
SYS_BOOT8: R90.1 R108.2 U15.U1 | length 905.8
  TopLayer - S1 (.GTL) w4.72: U15.U1@1167.28,893.78 1158.8,893.8 1146.65,881.65 1146.65,880.86 1123.11,857.31 1123.11,421.18 1286.79,257.5 v1(1402.5,257.5)
  BottomLayer - S8 (.GBL) w8: R90.1@1371.12,257.5 v1(1402.5,257.5) R108.2@1433.88,257.5
SYS_BOOT9: R89.1 R107.2 U15.U2 | length 1126.9
  TopLayer - S1 (.GTL) w4.72: U15.U2@1198.78,893.78 1190.83,885.83 1181.79,885.83 1175.15,879.19 1160.19,879.19 1133.86,852.86 1133.86,431.1 1286.46,278.5 1601.5,278.5 v1(1622.5,257.5)
  BottomLayer - S8 (.GBL) w8: R107.2@1591.12,257.5 v1(1622.5,257.5) R89.1@1653.88,257.5
SYS_BOOT10: R88.1 R106.2 U15.U3 | length 882.5
  TopLayer - S1 (.GTL) w4.72: U15.U3@1230.28,893.78 1214.51,878.03 1195.27,878.03 1193.58,876.35 1187.85,876.35 1184.16,872.66 1184.16,845.57 1144.61,806.03 1144.61,440.04 1284.65,300 v1(1402.5,300)
  BottomLayer - S8 (.GBL) w8: R88.1@1371.12,300 v1(1402.5,300) R106.2@1433.88,300
SYS_BOOT11: R87.1 R105.2 U15.U4 | length 1005
  TopLayer - S1 (.GTL) w4.72: U15.U4@1261.77,893.78 1246.04,878.07 1246.04,798.2 1240.12,792.29 1240.12,480.86 1347.48,373.5 1445.5,373.5 1454.5,364.5 1634.5,364.5 1644.5,354.5 1644.5,322 v1(1622.5,300)
  BottomLayer - S8 (.GBL) w8: R105.2@1591.12,300 v1(1622.5,300) R87.1@1653.88,300
SYS_BOOT12: R86.1 R104.2 U15.V2 | length 783.6
  TopLayer - S1 (.GTL) w4.72: U15.V2@1198.78,862.28 1198.78,841.5 1155.36,798.07 1155.36,451.93 1264.78,342.5 v1(1402.5,342.5)
  BottomLayer - S8 (.GBL) w8: R86.1@1371.12,342.5 v1(1402.5,342.5) R104.2@1433.88,342.5
SYS_BOOT13: R85.1 R103.2 U15.V3 | length 916.1
  TopLayer - S1 (.GTL) w4.72: U15.V3@1230.28,862.28 1230.28,797.64 1229.38,796.74 1229.38,474.63 1342.51,361.5 1421.68,361.5 1461.68,321.5 1545.5,321.5 1566.5,342.5 v1(1622.5,342.5)
  BottomLayer - S8 (.GBL) w8: R103.2@1591.12,342.5 v1(1622.5,342.5) R85.1@1653.88,342.5
SYS_BOOT14: R84.1 R102.2 U15.V4 | length 636.4
  TopLayer - S1 (.GTL) w4.72: U15.V4@1261.77,862.28 1261.77,790.32 1250.88,779.42 1250.88,487.08 1345.45,392.5 v1(1402.5,392.5)
  BottomLayer - S8 (.GBL) w8: R84.1@1371.12,392.5 v1(1402.5,392.5) 1426.38,392.5 R102.2@1433.88,385
SYS_BOOT15: R83.1 R101.2 U15.T5 | length 913.6
  TopLayer - S1 (.GTL) w4.72: U15.T5@1293.27,925.28 1278,910.01 1278,784.89 1261.62,768.51 1261.62,493.3 1340.92,414 1427,414 1434.5,406.5 1601,406.5 v1(1622.5,385)
  BottomLayer - S8 (.GBL) w8: R101.2@1591.12,385 v1(1622.5,385) R83.1@1653.88,385
SYS_RESETN: R70.1 R71.1 R164.1 U11.2 U15.A10 U24.4 | length 1426.2
  TopLayer - S1 (.GTL) w4.75: U15.A10@1450.75,1397.72 1450.75,1410.77 1460,1420.03 1460,1504.29 v2(1498.03,1542.32) 1531.32,1542.32 1537.5,1548.5 1537.5,1561.12 R70.1@1548.88,1572.5 1550,1573.62 R71.1@1550,1631
  TopLayer - S1 (.GTL) w5.91: U24.4@1861.91,2087.6 1861.91,2034.15 1843.6,2015.85 v1(1843.6,1837.5) U11.2@1880.1,1837.5
  BottomLayer - S8 (.GBL) w5.91: v2(1498.03,1542.32) 1664.37,1542.32 1843.6,1721.56 v1(1843.6,1837.5)
  BottomLayer - S8 (.GBL) w5.94: R164.1@1600,1868.5 R164.1@1600,1866 1600,1826.18 1614.17,1812.01 1731.3,1812.01 1756.79,1837.5 v1(1843.6,1837.5)
SYS_WARMRESETN: R71.2 S1.2 | length 249.5
  TopLayer - S1 (.GTL) w4.75: R71.2@1550,1694 1550,1735 1589,1774 1725.93,1774 S1.2@1737.5,1785.57
TCK: J8.11 R160.2 | length 111.5
  TopLayer - S1 (.GTL) w5.91: v1(1487.5,2002.26) J8.11@1487.5,2075
  BottomLayer - S8 (.GBL) w5.91: v1(1487.5,2002.26) R160.2@1487.5,2041
TDIS: J8.4 R151.2 | length 106.8
  TopLayer - S1 (.GTL) w5.91: J8.4@1287.5,2210.04 v1(1287.5,2283.96)
  BottomLayer - S8 (.GBL) w5.91: R151.2@1287.5,2251.12 v1(1287.5,2283.96)
USB_EARTH: J7.MP1 J7.MP2 J7.MP3 J7.MP4 L10.2 | length 411
  TopLayer - S1 (.GTL) w19.68: J7.MP4@2634.86,3682.91 2636.95,3685 L10.2@3045,3685
USBD_FT_N: L8.2 U22.7 | length 312.4
  TopLayer - S1 (.GTL) w5.12: U22.7@2604.53,3231 2604.53,3269 2601.38,3272.15 2601.38,3464.57 2623.03,3486.22 2644.68,3486.22 2648.62,3482.28 2661.04,3482.28 L8.2@2666.16,3477.17
USBD_FT_P: L8.1 U22.8 | length 334.5
  TopLayer - S1 (.GTL) w5.12: U22.8@2584.84,3231 2584.84,3269 2587.99,3272.15 2587.99,3470.11 2617.49,3499.61 2644.29,3499.61 2648.62,3503.94 2661.44,3503.94 L8.1@2666.16,3508.66
USBD_N: J7.2 L8.3 U21.2 | length 166.4
  TopLayer - S1 (.GTL) w5.12: L8.3@2739,3477.17 2744.25,3482.42 2756.5,3482.42 2760.24,3486.16 ; 2760.24,3486.22 2774.3,3486.22 2783.48,3495.41 v1(2792.39,3495.41) 2792.39,3504.31 2801.87,3513.79 2801.87,3534.37 2803.94,3536.44 2803.94,3566.56 J7.2@2808.09,3570.71
  BottomLayer - S8 (.GBL) w7.87: v1(2792.39,3495.41) 2792.5,3495.3 U21.2@2792.5,3473.76 U21.2@2792.5,3471.81
USBD_P: J7.3 L8.4 U21.1 | length 165.4
  TopLayer - S1 (.GTL) w5.12: L8.4@2739,3508.66 2744.17,3503.48 2756.36,3503.48 2760.24,3499.61 2768.75,3499.61 2774.02,3504.87 v1(2774.02,3513.78) 2782.92,3513.78 2788.48,3519.34 2788.48,3534.61 2786.42,3536.67 2786.42,3566.79 J7.3@2782.5,3570.71
  BottomLayer - S8 (.GBL) w7.87: U21.1@2772.81,3470.83 2771.06,3472.58 2771.06,3510.83 v1(2774.02,3513.78)
V5__DC_SITARA: C22.2 C80.1 C81.1 C82.1 C83.1 C84.1 C85.1 C87.1 C89.1 C100.1 J1.2 R3.2 R8.1 R10.1 U5.4 U13.3 U13.6 U13.13 U13.23 U13.27 U13.28 U13.36 U13.41 U13.47 U14.4 U14.6 | length 5494.7
  TopLayer - S1 (.GTL) w7.87: v1(2710.63,2491.14) 2710.63,2441.93 2715.59,2436.97 U5.4@2715.59,2422.39
  TopLayer - S1 (.GTL) w8: v1@446.87,2261.87 462,2261.87 ; v1@451,2251 451.55,2251.43 462,2261.87 ; v1@453.12,2309.12 460.88,2309.12 U13.3@480.83,2309.12 ; U13.6@480.83,2261.87 462,2261.87 ; 511,2395 524.13,2381.87 ; U13.41@618.62,2368.17 618.62,2390.13 ; 633,2421 618.62,2406.62 618.62,2390.13 ; 639.49,2411 618.62,2390.13 ; U13.23@665.87,2139.83 665.87,2127.88 v1(681.75,2112) ; U13.27@709.17,2198.88 721.12,2198.88 732.28,2187.72 ; U13.28@709.17,2214.63 v1(737,2214.63) ; U13.36@709.17,2340.61 700,2340.61 700,2353 706,2353 712,2353 U13.36@712,2341 ; v1@732.28,2178.15 732.28,2187.72 ; v1@737,2183 732.28,2187.72
  TopLayer - S1 (.GTL) w9: 460.88,2309.12 452,2318 v1(448,2314) 447,2309 U13.3@490,2309 ; 511,2396 514,2396 524.13,2385.87 524.13,2381.87 U13.47@524.13,2368.17 U13.47@524.13,2360.12
  TopLayer - S1 (.GTL) w9.84: R3.2@268.62,2875 v1(307.5,2875)
  TopLayer - S1 (.GTL) w12: v1(501,2396) 501,2395 511,2395
  TopLayer - S1 (.GTL) w15: v1(490,2112) 490,2129 497,2136 U13.13@505,2136
  TopLayer - S1 (.GTL) w20: 625,2405 655,2435 C81.1@655,2438.5 663.5,2430 v1(693,2430) ; 706,2347 706,2353 706,2385 721,2400 721,2431 C80.1@737,2431 ; C80.1@730,2438.5 739.5,2448 v1(767,2448)
  TopLayer - S1 (.GTL) w23.62: v3(2130.91,2339.57) 2130.91,2305.1 R10.1@2138.5,2297.5
  TopLayer - S1 (.GTL) w31.5: R8.1@1906.5,2339 v3(1990.57,2339)
  MidLayer2 - S3 (.G2) w9.84: v1(307.5,2875) 549.21,2633.29 549.21,2540.35 592.52,2497.05 759.84,2497.05 v1(801.18,2455.71)
  MidLayer5 - S6 (.G5) w7.87: v3(2130.91,2339.57) 2450.79,2339.57 2602.36,2491.14 v1(2710.63,2491.14)
  BottomLayer - S8 (.GBL) w8: U14.4@1190.79,1795.31 1190.79,1816.01 1195.9,1821.12 1204.15,1821.12 1204.73,1821.69 1229.47,1821.69 ; U14.6@1230.16,1795.31 1235.47,1800.63
  BottomLayer - S8 (.GBL) w15: C85.1@489,2215 C85.1@493.5,2215 ; C83.1@493.5,2360 C83.1@501,2367.5 ; v1(681.75,2112) 681.75,2065 C84.1@693.5,2065 ; C87.1@696.5,2215 696.5,2214.63 v1(737,2214.63)
  BottomLayer - S8 (.GBL) w15.75: 1072.83,2435.04 1072.83,2060.04 1234.25,1898.62 1234.25,1859.41 C100.1@1241.97,1851.69
  BottomLayer - S8 (.GBL) w20: v1(448,2256) 472,2256 473,2257 ; v1(448,2314) 484,2314 ; C89.1@484,2157.5 C85.1@484,2215 ; C85.1@489,2215 C85.1@484,2215 ; v1(490,2112) 490,2157.5 C89.1@493.5,2157.5 ; C83.1@493.5,2360 484,2360 484,2314 ; C83.1@501,2367.5 v1(501,2396) ; 1235.47,1791.69 1235.47,1800.63 1235.47,1845.2 C100.1@1241.97,1851.69 ; 473,2257 484,2268 ; 473,2257 484,2246 ; C85.1@484,2215 484,2246 ; 484,2246 484,2268 ; 484,2268 484,2314
  BottomLayer - S8 (.GBL) w31.5: v3(1990.57,2339) 2130.33,2339 v3(2130.91,2339.57)
  BottomLayer - S8 (.GBL) w39.37: 807.09,2446.85 1072.83,2446.85 1438.48,2812.5 J1.2@1830,2812.5 2061.02,2581.48 2061.02,2344.49
  other v1: 737.2,2178.15 801.18,2437.99 818.9,2437.99 818.9,2455.71
V11PHY: C23.1 C45.1 C46.1 C47.1 C48.1 C49.1 C50.1 C72.1 C73.1 C74.1 C75.1 C76.1 C77.1 U5.1 U6.8 U6.29 U6.42 U6.58 U12.8 U12.29 U12.42 U12.58 | length 2408.6
  TopLayer - S1 (.GTL) w10: U12.8@2681,515.16 v1(2728.9,515.16) 2728.9,515 C74.1@2752.01,515 ; U6.8@2681,1612.66 v1(2728.9,1612.66) 2728.9,1612.5 C47.1@2752.01,1612.5
  TopLayer - S1 (.GTL) w12: U6.42@2244,1592.97 v2(2289,1592.97) ; U12.42@2267.72,495.47 v2(2289,495.47) ; v2(2373.92,698.5) U12.29@2373.92,743.5 ; v2(2373.92,1796) U6.29@2373.92,1841 ; U12.58@2492.03,306.5 v2(2492.03,351.5) ; U6.58@2492.03,1404 v2(2492.03,1449) ; U5.1@2664.41,2345.61 2664.41,2306.09 C23.1@2676.5,2294
  TopLayer - S1 (.GTL) w20: v3@2676.5,2241.5 C23.1@2676.5,2294
  MidLayer4 - S5 (.G4) w10: v2(2289,495.47) 2289,524.75 2464.25,524.75 ; v2(2289,1592.97) 2289,1622.25 2464.25,1622.25 ; 2464.25,696.5 2464.25,524.75 ; 2464.25,1794 2464.25,1622.25 ; v2(2492.03,351.5) 2492.03,372.75 2464.25,372.75 2464.25,524.75 ; v2(2492.03,1449) 2492.03,1470.25 2464.25,1470.25 2464.25,1622.25 ; 2607,524.75 2464.25,524.75 ; 2607,1622.25 2464.25,1622.25
  MidLayer4 - S5 (.G4) w23.62: 2633,515.16 v1(2728.9,515.16) ; 2633,1612.66 v1(2728.9,1612.66)
  BottomLayer - S8 (.GBL) w10: C76.1@2267.5,492.01 2270.96,495.47 v2(2289,495.47) ; C49.1@2267.5,1589.51 2270.96,1592.97 v2(2289,1592.97) ; v2(2492.03,351.5) 2492.03,333.46 C77.1@2495.49,330 ; v2(2492.03,1449) 2492.03,1430.96 C50.1@2495.49,1427.5
  BottomLayer - S8 (.GBL) w12: v2(2373.92,698.5) 2399.51,698.5 C75.1@2399.51,700 ; v2(2373.92,1796) 2399.51,1796 C48.1@2399.51,1797.5
  BottomLayer - S8 (.GBL) w15: v1(2287,700) C73.1@2314.51,700 ; v1(2287,747.5) C72.1@2326,747.5 ; v1(2287,1797.5) C46.1@2314.51,1797.5 ; v1(2287,1845) C45.1@2326,1845
  other v3: 2666,2240 2690,2240
V18CDC: C260.1 L13.1 R169.2 R177.2 R178.2 U13.7 | length 4409.4
  TopLayer - S1 (.GTL) w10.01: C260.1@414,2235 456.5,2235 ; C260.1@415,2228.5 450,2228.5 456.5,2235 ; U13.7@489,2246.13 U13.7@480.83,2246.13 467.63,2246.13 456.5,2235
  TopLayer - S1 (.GTL) w15.75: v1(394.5,2191) 394.5,2213 C260.1@406.5,2225
  MidLayer5 - S6 (.G5) w15.75: 1073.5,2075 2090.59,2075 2247.5,1918.09 2247.5,1545.5 2373.5,1419.5 2540,1419.5 2578.88,1380.62 2578.88,1265.88 2523,1210 2523,1155.5 v1(2507.5,1140) v1(2507.5,1097.5) v1(2507.5,1055) 2536,1026.5 2768.5,1026.5 2785,1010 3000,1010 3109.5,1119.5 v1(3185.5,1119.5)
  MidLayer5 - S6 (.G5) w19.68: v1(394.5,2191) 363.19,2222.31 363.19,2310.04 393.15,2340 550.63,2340 562.99,2352.36 631.89,2352.36 652.56,2331.69 816.81,2331.69 1073.5,2075
  BottomLayer - S8 (.GBL) w11.81: R169.2@2476.12,1055 v1(2507.5,1055) ; R177.2@2476.12,1097.5 v1(2507.5,1097.5) ; R178.2@2476.12,1140 v1(2507.5,1140) ; v1(3185.5,1119.5) 3224,1119.5 3230,1113.5 L13.1@3230,1091.12
V25PHY: C36.1 C37.1 C38.1 C39.1 C63.1 C64.1 C65.1 C66.1 R9.2 R13.2 U6.4 U6.12 U12.4 U12.12 | length 3095.9
  TopLayer - S1 (.GTL) w9.84: R13.2@268.62,2825 v1(307.5,2825)
  TopLayer - S1 (.GTL) w12: U12.4@2681,436.42 v1(2728.9,436.42) C66.1@2752.01,436.42 ; U12.12@2681,593.9 v1(2728.9,593.9) C65.1@2752.01,593.9 ; U6.4@2681,1533.92 v1(2728.9,1533.92) C38.1@2752.01,1533.92 ; U6.12@2681,1691.4 v1(2728.9,1691.4) C39.1@2752.01,1691.4
  TopLayer - S1 (.GTL) w31.5: R9.2@2676.5,2614 v3(2756,2614) v3(2780,2614)
  MidLayer5 - S6 (.G5) w9.84: v1(307.5,2825) 447.55,2684.95 2352.45,2684.95 2423.4,2614 v3(2756,2614)
  BottomLayer - S8 (.GBL) w15: C64.1@2725,619.51 2725,597.8 v1(2728.9,593.9) 2757.89,593.9 C63.1@2765,601 ; C37.1@2725,1717.01 2725,1695.3 v1(2728.9,1691.4) 2755.39,1691.4 C36.1@2765,1701
VAUX1: C95.1 C134.1 C135.1 U13.46 U15.N16 U15.R16 | length 2648.5
  TopLayer - S1 (.GTL) w6: U15.R16@1639.72,956.77 v2(1655.47,941.02) ; U15.N16@1639.72,1019.76 v2(1655.47,1004.02)
  TopLayer - S1 (.GTL) w9: U13.46@539.88,2360.12 U13.46@539.88,2368.17 539.88,2382.87 ; v3@544.88,2396 539.88,2391 539.88,2382.87 ; v3@550.2,2392.72 539.88,2382.87
  TopLayer - S1 (.GTL) w15.75: v1(1016,784) v1(1034,784)
  MidLayer1 - S2 (.G1) w5.51: 1326.18,1012.6 1333.46,1019.88 1361.81,1019.88 1364.76,1016.93
  MidLayer1 - S2 (.G1) w15: 1488.5,1005 1497,1013.5 1602.5,1013.5 1613.5,1024.5 1634.99,1024.5 v2(1655.47,1004.02)
  MidLayer2 - S3 (.G2) w47.24: 347.69,2106.69 202.5,1961.5 202.5,883.5 301.5,784.5 v1@1021.5,784.5
  MidLayer5 - S6 (.G5) w15: v2(1655.47,941.02) v2(1655.47,1004.02)
  BottomLayer - S8 (.GBL) w15: v2(1655.47,941.02) 1680.98,941.02 C134.1@1682.01,940 ; v2(1655.47,1004.02) 1681.02,1004.02 C135.1@1682.01,1005
  BottomLayer - S8 (.GBL) w20: v3(546.26,2399.61) 546.26,2432.26 C95.1@556.5,2442.5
